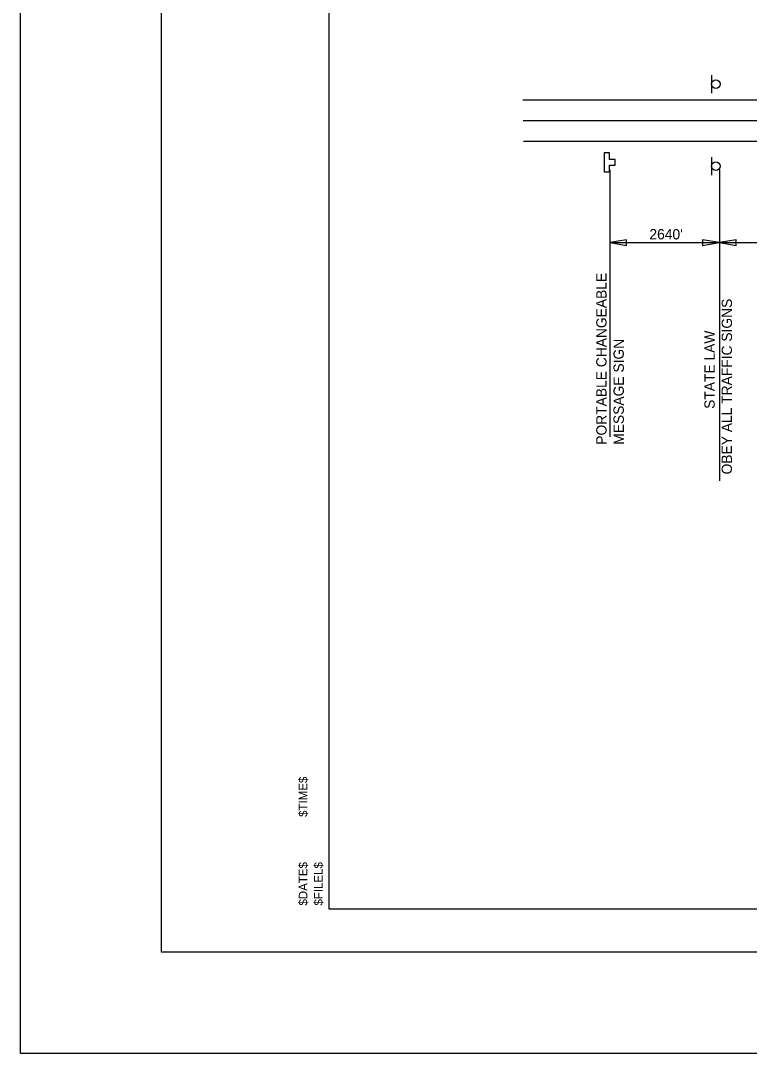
# Model space of a CAD drawing. Extents: x 2155255 to 2162649, y 140388 to 141878.
# Drawn here: x 2156155 to 2156579, y 140388 to 140988 of the extents above; entities that cross this region are included whole.
import ezdxf

# ---------------------------------------------------------------- set-up
doc = ezdxf.new("R2010")
doc.units = 0
for name, color, linetype in [('Default', 7, 'Continuous'), ('PR_Dimensions1', 7, 'Continuous'), ('PR_Traffic_Control_Devices_Temp', 7, 'Continuous'), ('PR_Traffic_Temp_Txt', 7, 'Continuous'), ('SHT_Plot_Shape_Full', 7, 'Continuous'), ('SHT_Plot_Shape_Half', 7, 'Continuous'), ('SHT_Plot_Stamp', 7, 'Continuous'), ('SHT_Sheet_Border', 7, 'Continuous'), ('SHT_Standard_Sheet_Txt', 7, 'Continuous'), ('TOPO_Asphalt', 7, 'Continuous')]:
    doc.layers.add(name, color=color, linetype=linetype)

# ---------------------------------------------------------------- blocks, each defined once
blk = doc.blocks.new('Stamp_Plot_Stamp')
at = {"layer": 'SHT_Plot_Stamp'}
for s, p in [('$TIME$', (1.695, 1.572)), ('$DATE$', (1.695, 0.542)), ('$FILEL$', (1.873, 0.542))]:
    blk.add_text(s, height=0.1, rotation=90, dxfattribs=at).set_placement(p)
blk = doc.blocks.new('TCSIGN')
at = {"layer": 'Default'}
blk.add_line((5.26, 2.5), (-5.26, 2.5), dxfattribs=at)
blk.add_circle((0, 0), 2.5, dxfattribs=at)
blk = doc.blocks.new('Arrowhd')
at = {"layer": 'Default'}
blk.add_lwpolyline([(0.318, -0.053), (0.318, 0.053), (0, 0)], close=True, dxfattribs=at)
blk = doc.blocks.new('PR-TCSIGN_rev')
at = {"layer": 'Default'}
blk.add_lwpolyline([(-5.47, 0), (-1.58, 0), (-1.58, -3.22), (1.58, -3.22), (1.58, 0), (5.47, 0), (5.47, 3.06), (-5.47, 3.06)], close=True, dxfattribs=at)
blk.add_lwpolyline([(1.58, 0), (5.47, 0), (5.47, 3.06), (-5.47, 3.06), (-5.47, 0), (-1.58, 0), (-1.58, -3.22), (1.58, -3.22), (1.58, 0)], dxfattribs=at)

msp = doc.modelspace()

# ---------------------------------------------------------------- linework, layer by layer
at = {"layer": 'PR_Dimensions1'}
for p, q in [((2156497.72, 140901.56), (2156497.72, 140746.34)), ((2156561.46, 140901.56), (2156561.46, 140720.72)), ((2156497.72, 140859.25), (2156561.46, 140859.25)), ((2156561.46, 140859.25), (2156631.06, 140859.25))]:
    msp.add_line(p, q, dxfattribs=at)
at = {"layer": 'SHT_Plot_Shape_Full'}
msp.add_lwpolyline([(2156155.34, 141588.17), (2157955.34, 141588.17), (2157955.34, 140388.17), (2156155.34, 140388.17)], close=True, dxfattribs=at)
at = {"layer": 'SHT_Plot_Shape_Half'}
msp.add_lwpolyline([(2156237.22, 141546.92), (2157937.22, 141546.92), (2157937.22, 140446.92), (2156237.22, 140446.92)], close=True, dxfattribs=at)
at = {"layer": 'SHT_Sheet_Border'}
msp.add_lwpolyline([(2157909.72, 140471.92), (2156334.72, 140471.92), (2156334.72, 141521.92), (2157909.72, 141521.92)], close=True, dxfattribs=at)
at = {"layer": 'TOPO_Asphalt'}
for p, q in [((2157147.83, 140941.97), (2156447.24, 140941.97)), ((2157147.76, 140929.97), (2156447.37, 140929.97)), ((2157147.69, 140917.97), (2156447.51, 140917.97)), ((2157147.69, 140917.97), (2156447.51, 140917.97))]:
    msp.add_line(p, q, dxfattribs=at)

# ---------------------------------------------------------------- block references
at = {"layer": 'PR_Dimensions1', "xscale": 30.761459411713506, "yscale": 30.761459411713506}
for p in [(2156497.72, 140859.25), (2156561.46, 140859.25)]:
    msp.add_blockref('Arrowhd', p, dxfattribs=at)
at = {"layer": 'PR_Dimensions1', "xscale": 30.761459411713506, "yscale": 30.761459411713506, "rotation": 180}
msp.add_blockref('Arrowhd', (2156561.46, 140859.25), dxfattribs=at)
at = {"layer": 'PR_Traffic_Control_Devices_Temp', "rotation": 89.99999999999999}
for name, p in [('TCSIGN', (2156559.31, 140951.31)), ('PR-TCSIGN_rev', (2156497.57, 140905.88)), ('TCSIGN', (2156559.31, 140903.66))]:
    msp.add_blockref(name, p, dxfattribs=at)
at = {"layer": 'SHT_Standard_Sheet_Txt', "xscale": 50, "yscale": 50}
msp.add_blockref('Stamp_Plot_Stamp', (2156237.22, 140446.92), dxfattribs=at)

# ---------------------------------------------------------------- texts
at = {"layer": 'PR_Traffic_Temp_Txt'}
for s, rotation, p in [("2640'", 360, (2156520.75, 140861.07)), ('PORTABLE CHANGEABLE', 90, (2156495.86, 140741.78)), ('OBEY ALL TRAFFIC SIGNS', 90, (2156568.72, 140724.54)), ('STATE LAW', 90, (2156558.7, 140762.62)), ('MESSAGE SIGN', 90, (2156505.88, 140741.78))]:
    msp.add_text(s, height=6, rotation=rotation, dxfattribs=at).set_placement(p)

doc.saveas('drawing.dxf')
